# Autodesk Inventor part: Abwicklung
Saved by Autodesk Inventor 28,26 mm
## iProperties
Created: 2010-06
Part Number: Abwicklung
Material: 1.0038
Document SubType Name: Blech
Designer: LL
Stock Number: =<Type>
Density: 7.86 g/cm^3
Flat Pattern Width: 2.82619 cm
Flat Pattern Length: 10 cm
Flat Pattern Area: 28.2619 cm^2
Sheet Metal Rule: Standard
Sheet Metal Width: 100,00 mm
Sheet Metal Length: 2826,19 mm^2
Author: LL
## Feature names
1. Extrusion1
2. Grobblech1
3. Biegung1
